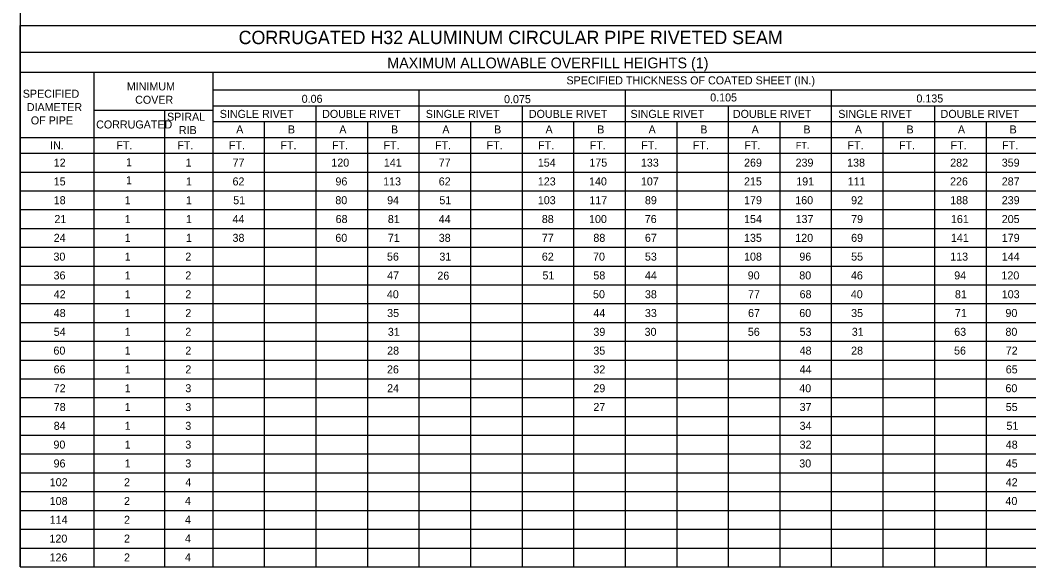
# Model space of a CAD drawing. Extents: x -439.1 to -407.9, y -458.1 to -436.2.
# Drawn here: x -439.11 to -420.2, y -458.05 to -447.81 of the extents above; entities that cross this region are included whole.
import ezdxf

# ---------------------------------------------------------------- set-up
doc = ezdxf.new("R2010")
doc.units = 0
doc.layers.add('Draft_Named_Boundary', color=7, linetype='Continuous')
doc.layers.add('Level 4', color=7, linetype='Continuous')

msp = doc.modelspace()

# ---------------------------------------------------------------- linework, layer by layer
at = {"layer": 'Draft_Named_Boundary'}
msp.add_lwpolyline([(-439.109, -458.051), (-407.859, -458.051), (-407.859, -437.676), (-439.109, -437.676)], close=True, dxfattribs=at)
at = {"layer": 'Level 4'}
for p, q in [((-439.109, -447.908), (-416.17, -447.908)), ((-439.109, -458.051), (-439.109, -447.908)), ((-439.109, -448.409), (-416.17, -448.409)), ((-439.109, -448.785), (-416.17, -448.785)), ((-437.72, -458.051), (-437.72, -448.785)), ((-435.493, -458.051), (-435.493, -448.785)), ((-435.493, -449.113), (-416.17, -449.113)), ((-431.629, -458.051), (-431.629, -449.113)), ((-427.764, -458.051), (-427.764, -449.113)), ((-423.9, -458.051), (-423.9, -449.113)), ((-437.72, -449.495), (-435.493, -449.495)), ((-436.396, -458.051), (-436.396, -449.495)), ((-435.493, -449.411), (-416.17, -449.411)), ((-433.561, -458.051), (-433.561, -449.411)), ((-429.696, -458.051), (-429.696, -449.411)), ((-425.832, -458.051), (-425.832, -449.411)), ((-421.967, -458.051), (-421.967, -449.411)), ((-435.493, -449.708), (-416.17, -449.708)), ((-434.527, -458.051), (-434.527, -449.708)), ((-432.595, -458.051), (-432.595, -449.708)), ((-430.663, -458.051), (-430.663, -449.708)), ((-428.73, -458.051), (-428.73, -449.708)), ((-426.798, -458.051), (-426.798, -449.708)), ((-424.866, -458.051), (-424.866, -449.708)), ((-422.933, -458.051), (-422.933, -449.708)), ((-421.001, -458.051), (-421.001, -449.708)), ((-439.109, -450.005), (-416.17, -450.005)), ((-439.109, -450.302), (-416.17, -450.302)), ((-439.109, -450.654), (-416.17, -450.654)), ((-439.109, -451.006), (-416.17, -451.006)), ((-439.109, -451.359), (-416.17, -451.359)), ((-439.109, -451.711), (-416.17, -451.711)), ((-439.109, -452.063), (-416.17, -452.063)), ((-439.109, -452.415), (-416.17, -452.415)), ((-439.109, -452.767), (-416.17, -452.767)), ((-439.109, -453.12), (-416.17, -453.12)), ((-439.109, -453.472), (-416.17, -453.472)), ((-439.109, -453.824), (-416.17, -453.824)), ((-439.109, -454.176), (-416.17, -454.176)), ((-439.109, -454.529), (-416.17, -454.529)), ((-439.109, -454.881), (-416.17, -454.881)), ((-439.109, -455.233), (-416.17, -455.233)), ((-439.109, -455.585), (-416.17, -455.585)), ((-439.109, -455.937), (-416.17, -455.937)), ((-439.109, -456.29), (-416.17, -456.29)), ((-439.109, -456.642), (-416.17, -456.642)), ((-439.109, -456.994), (-416.17, -456.994)), ((-439.109, -457.346), (-416.17, -457.346)), ((-439.109, -457.699), (-416.17, -457.699)), ((-439.109, -458.051), (-416.17, -458.051))]:
    msp.add_line(p, q, dxfattribs=at)

# ---------------------------------------------------------------- texts
for s, height, p in [('CORRUGATED H32 ALUMINUM CIRCULAR PIPE RIVETED SEAM', 0.25, (-435.015, -448.258)), ('MAXIMUM ALLOWABLE OVERFILL HEIGHTS (1)', 0.2, (-432.228, -448.71)), ('MINIMUM', 0.15, (-437.11, -449.125)), ('SPECIFIED THICKNESS OF COATED SHEET (IN.)', 0.15, (-428.87, -449.012)), ('SPECIFIED', 0.15, (-439.06, -449.262)), ('COVER', 0.15, (-436.954, -449.375)), ('0.06', 0.15, (-433.833, -449.357)), ('0.075', 0.15, (-430.04, -449.364)), ('0.105', 0.15, (-426.176, -449.332)), ('0.135', 0.15, (-422.311, -449.351)), ('DIAMETER', 0.15, (-438.985, -449.512)), ('SPIRAL', 0.15, (-436.356, -449.693)), ('SINGLE RIVET', 0.15, (-435.368, -449.64)), ('DOUBLE RIVET', 0.15, (-433.449, -449.64)), ('SINGLE RIVET', 0.15, (-431.506, -449.64)), ('DOUBLE RIVET', 0.15, (-429.575, -449.64)), ('SINGLE RIVET', 0.15, (-427.67, -449.64)), ('DOUBLE RIVET', 0.15, (-425.751, -449.64)), ('SINGLE RIVET', 0.15, (-423.776, -449.64)), ('DOUBLE RIVET', 0.15, (-421.858, -449.64)), ('OF PIPE', 0.15, (-438.909, -449.762)), ('CORRUGATED', 0.15, (-437.685, -449.838)), ('RIB', 0.15, (-436.135, -449.943)), ('A', 0.15, (-435.06, -449.931)), ('B', 0.15, (-434.091, -449.931)), ('A', 0.15, (-433.128, -449.931)), ('B', 0.15, (-432.159, -449.931)), ('A', 0.15, (-431.196, -449.931)), ('B', 0.15, (-430.227, -449.931)), ('A', 0.15, (-429.263, -449.931)), ('B', 0.15, (-428.294, -449.931)), ('A', 0.15, (-427.331, -449.931)), ('B', 0.15, (-426.362, -449.931)), ('A', 0.15, (-425.399, -449.931)), ('B', 0.15, (-424.43, -449.931)), ('A', 0.15, (-423.466, -449.931)), ('B', 0.15, (-422.498, -449.931)), ('A', 0.15, (-421.534, -449.931)), ('B', 0.15, (-420.565, -449.931)), ('IN.', 0.15, (-438.548, -450.228)), ('FT.', 0.15, (-437.306, -450.228)), ('FT.', 0.15, (-436.164, -450.228)), ('FT.', 0.15, (-435.197, -450.228)), ('FT.', 0.15, (-434.231, -450.228)), ('FT.', 0.15, (-433.265, -450.228)), ('FT.', 0.15, (-432.299, -450.228)), ('FT.', 0.15, (-431.333, -450.228)), ('FT.', 0.15, (-430.367, -450.228)), ('FT.', 0.15, (-429.401, -450.228)), ('FT.', 0.15, (-428.434, -450.228)), ('FT.', 0.15, (-427.468, -450.228)), ('FT.', 0.15, (-426.502, -450.228)), ('FT.', 0.15, (-425.536, -450.228)), ('FT.', 0.1265, (-424.57, -450.217)), ('FT.', 0.15, (-423.604, -450.228)), ('FT.', 0.15, (-422.638, -450.228)), ('FT.', 0.15, (-421.671, -450.228)), ('FT.', 0.15, (-420.705, -450.228)), ('12', 0.15, (-438.48, -450.553)), ('1', 0.15, (-437.125, -450.545)), ('1', 0.15, (-436.008, -450.553)), ('77', 0.15, (-435.129, -450.553)), ('120', 0.15, (-433.277, -450.553)), ('141', 0.15, (-432.293, -450.553)), ('77', 0.15, (-431.264, -450.553)), ('154', 0.15, (-429.407, -450.553)), ('175', 0.15, (-428.441, -450.553)), ('133', 0.15, (-427.475, -450.553)), ('269', 0.15, (-425.542, -450.553)), ('239', 0.15, (-424.576, -450.553)), ('138', 0.15, (-423.61, -450.553)), ('282', 0.15, (-421.678, -450.553)), ('359', 0.15, (-420.712, -450.553)), ('15', 0.15, (-438.48, -450.905)), ('1', 0.15, (-437.125, -450.882)), ('1', 0.15, (-436.001, -450.905)), ('62', 0.15, (-435.129, -450.905)), ('96', 0.15, (-433.2, -450.905)), ('113', 0.15, (-432.306, -450.905)), ('62', 0.15, (-431.264, -450.905)), ('123', 0.15, (-429.407, -450.905)), ('140', 0.15, (-428.447, -450.905)), ('107', 0.15, (-427.475, -450.905)), ('215', 0.15, (-425.543, -450.905)), ('191', 0.15, (-424.564, -450.905)), ('111', 0.15, (-423.598, -450.905)), ('226', 0.15, (-421.681, -450.905)), ('287', 0.15, (-420.712, -450.905)), ('18', 0.15, (-438.48, -451.257)), ('1', 0.15, (-437.15, -451.257)), ('1', 0.15, (-436.001, -451.257)), ('51', 0.15, (-435.116, -451.257)), ('80', 0.15, (-433.202, -451.257)), ('94', 0.15, (-432.231, -451.257)), ('51', 0.15, (-431.252, -451.257)), ('103', 0.15, (-429.407, -451.257)), ('117', 0.15, (-428.441, -451.257)), ('89', 0.15, (-427.4, -451.257)), ('179', 0.15, (-425.542, -451.257)), ('160', 0.15, (-424.582, -451.257)), ('92', 0.15, (-423.535, -451.257)), ('188', 0.15, (-421.678, -451.257)), ('239', 0.15, (-420.712, -451.257)), ('21', 0.15, (-438.467, -451.61)), ('1', 0.15, (-437.15, -451.61)), ('1', 0.15, (-436.001, -451.61)), ('44', 0.15, (-435.129, -451.61)), ('68', 0.15, (-433.197, -451.61)), ('81', 0.15, (-432.218, -451.61)), ('44', 0.15, (-431.264, -451.61)), ('88', 0.15, (-429.332, -451.61)), ('100', 0.15, (-428.447, -451.61)), ('76', 0.15, (-427.403, -451.61)), ('154', 0.15, (-425.542, -451.61)), ('137', 0.15, (-424.576, -451.61)), ('79', 0.15, (-423.535, -451.61)), ('161', 0.15, (-421.665, -451.61)), ('205', 0.15, (-420.712, -451.61)), ('24', 0.15, (-438.48, -451.962)), ('1', 0.15, (-437.15, -451.962)), ('1', 0.15, (-436.001, -451.962)), ('38', 0.15, (-435.129, -451.962)), ('60', 0.15, (-433.202, -451.962)), ('71', 0.15, (-432.218, -451.962)), ('38', 0.15, (-431.264, -451.962)), ('77', 0.15, (-429.332, -451.962)), ('88', 0.15, (-428.366, -451.962)), ('67', 0.15, (-427.4, -451.962)), ('135', 0.15, (-425.543, -451.962)), ('120', 0.15, (-424.582, -451.962)), ('69', 0.15, (-423.535, -451.962)), ('141', 0.15, (-421.665, -451.962)), ('179', 0.15, (-420.712, -451.962)), ('30', 0.15, (-438.485, -452.314)), ('1', 0.15, (-437.15, -452.314)), ('2', 0.15, (-436.014, -452.314)), ('56', 0.15, (-432.234, -452.314)), ('31', 0.15, (-431.252, -452.314)), ('62', 0.15, (-429.332, -452.314)), ('70', 0.15, (-428.372, -452.314)), ('53', 0.15, (-427.4, -452.314)), ('108', 0.15, (-425.542, -452.314)), ('96', 0.15, (-424.505, -452.314)), ('55', 0.15, (-423.535, -452.314)), ('113', 0.15, (-421.678, -452.314)), ('144', 0.15, (-420.712, -452.314)), ('36', 0.15, (-438.483, -452.666)), ('1', 0.15, (-437.15, -452.666)), ('2', 0.15, (-436.014, -452.666)), ('47', 0.15, (-432.231, -452.666)), ('26', 0.15, (-431.29, -452.671)), ('51', 0.15, (-429.32, -452.666)), ('58', 0.15, (-428.366, -452.666)), ('44', 0.15, (-427.4, -452.666)), ('90', 0.15, (-425.473, -452.666)), ('80', 0.15, (-424.507, -452.666)), ('46', 0.15, (-423.539, -452.666)), ('94', 0.15, (-421.603, -452.666)), ('120', 0.15, (-420.718, -452.666)), ('42', 0.15, (-438.48, -453.019)), ('1', 0.15, (-437.15, -453.019)), ('2', 0.15, (-436.014, -453.019)), ('40', 0.15, (-432.236, -453.019)), ('50', 0.15, (-428.372, -453.019)), ('38', 0.15, (-427.4, -453.019)), ('77', 0.15, (-425.467, -453.019)), ('68', 0.15, (-424.501, -453.019)), ('40', 0.15, (-423.541, -453.019)), ('81', 0.15, (-421.59, -453.019)), ('103', 0.15, (-420.712, -453.019)), ('48', 0.15, (-438.48, -453.371)), ('1', 0.15, (-437.15, -453.371)), ('2', 0.15, (-436.014, -453.371)), ('35', 0.15, (-432.231, -453.371)), ('44', 0.15, (-428.366, -453.371)), ('33', 0.15, (-427.4, -453.371)), ('67', 0.15, (-425.467, -453.371)), ('60', 0.15, (-424.507, -453.371)), ('35', 0.15, (-423.535, -453.371)), ('71', 0.15, (-421.59, -453.371)), ('90', 0.15, (-420.643, -453.371)), ('54', 0.15, (-438.48, -453.723)), ('1', 0.15, (-437.15, -453.723)), ('2', 0.15, (-436.014, -453.723)), ('31', 0.15, (-432.218, -453.723)), ('39', 0.15, (-428.366, -453.723)), ('30', 0.15, (-427.406, -453.723)), ('56', 0.15, (-425.471, -453.723)), ('53', 0.15, (-424.501, -453.723)), ('31', 0.15, (-423.523, -453.723)), ('63', 0.15, (-421.603, -453.723)), ('80', 0.15, (-420.643, -453.723)), ('60', 0.15, (-438.485, -454.075)), ('1', 0.15, (-437.15, -454.075)), ('2', 0.15, (-436.014, -454.075)), ('28', 0.15, (-432.231, -454.075)), ('35', 0.15, (-428.366, -454.075)), ('48', 0.15, (-424.501, -454.075)), ('28', 0.15, (-423.535, -454.075)), ('56', 0.15, (-421.606, -454.075)), ('72', 0.15, (-420.637, -454.075)), ('66', 0.15, (-438.483, -454.427)), ('1', 0.15, (-437.15, -454.427)), ('2', 0.15, (-436.014, -454.427)), ('26', 0.15, (-432.234, -454.427)), ('32', 0.15, (-428.366, -454.427)), ('44', 0.15, (-424.501, -454.427)), ('65', 0.15, (-420.637, -454.427)), ('72', 0.15, (-438.48, -454.78)), ('1', 0.15, (-437.15, -454.78)), ('3', 0.15, (-436.014, -454.78)), ('24', 0.15, (-432.231, -454.78)), ('29', 0.15, (-428.366, -454.78)), ('40', 0.15, (-424.507, -454.78)), ('60', 0.15, (-420.643, -454.78)), ('78', 0.15, (-438.48, -455.132)), ('1', 0.15, (-437.15, -455.132)), ('3', 0.15, (-436.014, -455.132)), ('27', 0.15, (-428.366, -455.132)), ('37', 0.15, (-424.501, -455.132)), ('55', 0.15, (-420.637, -455.132)), ('84', 0.15, (-438.48, -455.484)), ('1', 0.15, (-437.15, -455.484)), ('3', 0.15, (-436.014, -455.484)), ('34', 0.15, (-424.501, -455.484)), ('51', 0.15, (-420.624, -455.484)), ('90', 0.15, (-438.485, -455.836)), ('1', 0.15, (-437.15, -455.836)), ('3', 0.15, (-436.014, -455.836)), ('32', 0.15, (-424.501, -455.836)), ('48', 0.15, (-420.637, -455.836)), ('96', 0.15, (-438.483, -456.189)), ('1', 0.15, (-437.15, -456.189)), ('3', 0.15, (-436.014, -456.189)), ('30', 0.15, (-424.507, -456.189)), ('45', 0.15, (-420.637, -456.189)), ('102', 0.15, (-438.555, -456.541)), ('2', 0.15, (-437.163, -456.541)), ('4', 0.15, (-436.014, -456.541)), ('42', 0.15, (-420.637, -456.541)), ('108', 0.15, (-438.555, -456.893)), ('2', 0.15, (-437.163, -456.893)), ('4', 0.15, (-436.021, -456.89)), ('40', 0.15, (-420.643, -456.893)), ('114', 0.15, (-438.555, -457.245)), ('2', 0.15, (-437.163, -457.245)), ('4', 0.15, (-436.021, -457.243)), ('120', 0.15, (-438.56, -457.597)), ('2', 0.15, (-437.163, -457.597)), ('4', 0.15, (-436.021, -457.595)), ('126', 0.15, (-438.558, -457.95)), ('2', 0.15, (-437.163, -457.95)), ('4', 0.15, (-436.021, -457.947))]:
    msp.add_text(s, height=height, dxfattribs=at).set_placement(p)

doc.saveas('drawing.dxf')
